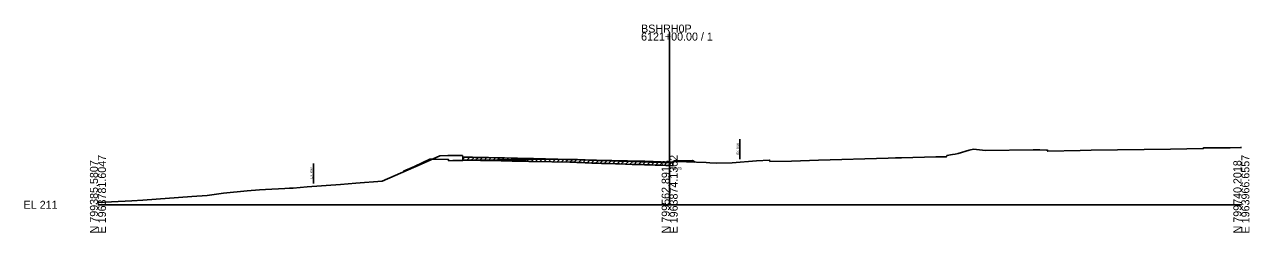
# Model space of a CAD drawing. Extents: x -26 to 1986619, y -10 to 827846.
# Drawn here: x -25.7 to 402.8, y 990.3 to 1063.1 of the extents above; entities that cross this region are included whole.
import ezdxf

# ---------------------------------------------------------------- set-up
doc = ezdxf.new("R2010")
doc.units = 0
for name, color, linetype in [('Default', 7, 'Continuous'), ('RD_EX_Road', 7, 'Continuous'), ('RD_PD_ALT5_LnLine', 7, 'Continuous'), ('RD_PD_ALT5_TrvlWay', 7, 'Continuous'), ('RD_PD_PaveDit', 7, 'Continuous'), ('RD_Sketch2', 7, 'Continuous'), ('RD_XS_ExRW', 7, 'Continuous')]:
    doc.layers.add(name, color=color, linetype=linetype)

msp = doc.modelspace()

# ---------------------------------------------------------------- linework, layer by layer
at = {"layer": 'RD_EX_Road'}
for p, q in [((200, 1000), (200, 1060.29)), ((0, 1000), (200, 1000)), ((200, 1000), (400, 1000))]:
    msp.add_line(p, q, dxfattribs=at)
at = {"layer": 'RD_PD_ALT5_LnLine'}
msp.add_lwpolyline([(0, 1000.83), (11.87, 1001.44), (15.66, 1001.6), (32.89, 1002.89), (38.19, 1003.26), (43.94, 1004.12), (52.18, 1004.88), (56.54, 1005.27), (58.65, 1005.33), (65.43, 1005.72), (66.98, 1005.8), (68.31, 1005.84), (73.24, 1006.29), (84.81, 1007.16), (90.27, 1007.58), (99.48, 1008.24), (113.12, 1014.24), (119.61, 1017.13), (122.4, 1017.3), (127.49, 1017.21), (127.59, 1016.75), (127.71, 1016.68), (128.51, 1016.69), (128.81, 1016.69), (129.12, 1016.68), (131.04, 1016.64), (132, 1016.61), (133.88, 1016.57), (136.64, 1016.53), (139.49, 1016.48), (140.33, 1016.47), (141.1, 1016.44), (142.25, 1016.41), (144.64, 1016.35), (145.06, 1016.34), (146.78, 1016.29), (147.92, 1016.27), (150.02, 1016.23), (150.74, 1016.21), (151.76, 1016.2), (152.38, 1016.21), (165.08, 1015.92), (166.86, 1015.88), (167.48, 1015.85), (167.8, 1015.83), (169.28, 1015.76), (170.48, 1015.7), (171.69, 1015.66), (172.75, 1015.62), (173.32, 1015.6), (175.07, 1015.54), (176.13, 1015.5), (177.53, 1015.47), (178.32, 1015.46), (178.95, 1015.45), (181, 1015.37), (181.77, 1015.35), (182.48, 1015.32), (184.58, 1015.24), (186.91, 1015.16), (187.84, 1015.13), (190.2, 1015.07), (191.25, 1015.04), (193.24, 1014.97), (194.95, 1014.92), (195.83, 1014.89), (196.81, 1014.86), (198.67, 1014.79), (200.24, 1014.75), (200.98, 1014.66), (201.06, 1014.75), (201.16, 1015.21), (202.12, 1015.19), (205.93, 1015.1), (212.76, 1014.8), (214.02, 1014.67), (216.39, 1014.64), (221.89, 1014.72), (230.43, 1015.41), (234.98, 1015.65), (235.08, 1015.2), (242.66, 1015.26), (252.01, 1015.61), (276.47, 1016.34), (279.02, 1016.46), (281.08, 1016.47), (293.09, 1016.76), (296.88, 1016.81), (296.98, 1017.26), (298.94, 1017.56), (299.9, 1017.74), (300.94, 1017.96), (304.8, 1019.16), (306.26, 1019.45), (310.5, 1019.01), (327.16, 1019.22), (329.09, 1019.25), (329.54, 1019.24), (331.8, 1019.19), (332.17, 1019.19), (332.27, 1018.74), (343.65, 1019.05), (347.49, 1019.09), (375.21, 1019.53), (386.67, 1019.69), (386.72, 1019.91), (396.1, 1019.99), (399.66, 1020.09), (400, 1020.1)], dxfattribs=at)
at = {"layer": 'RD_PD_PaveDit'}
for p, q in [((127.59, 1015.97), (127.59, 1016.97)), ((127.59, 1015.97), (128.32, 1016.69)), ((127.59, 1015.97), (127.71, 1015.68)), ((127.71, 1015.68), (128.51, 1015.69)), ((128.51, 1015.69), (128.81, 1015.69)), ((128.81, 1015.69), (129.12, 1015.68)), ((129.09, 1015.68), (130.07, 1016.66)), ((129.12, 1015.68), (131.04, 1015.64)), ((130.59, 1015.65), (131.57, 1016.62)), ((131.04, 1015.64), (132, 1015.61)), ((132.09, 1015.61), (133.07, 1016.59)), ((133.59, 1015.58), (134.58, 1016.56)), ((135.09, 1015.55), (136.08, 1016.54)), ((136.59, 1015.53), (137.58, 1016.51)), ((138.09, 1015.51), (139.08, 1016.49)), ((139.59, 1015.48), (140.57, 1016.46)), ((141.09, 1015.44), (142.07, 1016.41)), ((142.59, 1015.4), (143.57, 1016.37)), ((144.09, 1015.36), (145.07, 1016.34)), ((145.59, 1015.32), (146.57, 1016.29)), ((147.09, 1015.28), (148.08, 1016.26)), ((148.59, 1015.25), (149.58, 1016.24)), ((150.09, 1015.23), (151.08, 1016.21)), ((151.59, 1015.21), (152.6, 1016.21)), ((153.09, 1015.2), (154.07, 1016.18)), ((154.59, 1015.16), (155.57, 1016.14)), ((156.09, 1015.13), (157.07, 1016.11)), ((157.59, 1015.09), (158.57, 1016.07)), ((159.09, 1015.06), (160.07, 1016.04)), ((160.59, 1015.03), (161.57, 1016)), ((162.09, 1014.99), (163.07, 1015.97)), ((163.59, 1014.96), (164.57, 1015.93)), ((165.09, 1014.92), (166.07, 1015.9)), ((166.59, 1014.89), (167.55, 1015.84)), ((168.09, 1014.81), (169.05, 1015.77)), ((169.59, 1014.74), (170.55, 1015.7)), ((171.09, 1014.68), (172.06, 1015.64)), ((132, 1015.61), (133.88, 1015.57)), ((133.88, 1015.57), (136.64, 1015.53)), ((136.64, 1015.53), (139.49, 1015.48)), ((139.49, 1015.48), (140.33, 1015.47)), ((140.33, 1015.47), (141.1, 1015.44)), ((141.1, 1015.44), (142.25, 1015.41)), ((142.25, 1015.41), (144.64, 1015.35)), ((144.64, 1015.35), (145.06, 1015.34)), ((145.06, 1015.34), (146.78, 1015.29)), ((146.78, 1015.29), (147.92, 1015.27)), ((147.92, 1015.27), (150.02, 1015.23)), ((150.02, 1015.23), (150.74, 1015.21)), ((150.74, 1015.21), (151.76, 1015.2)), ((151.76, 1015.2), (152.38, 1015.21)), ((152.38, 1015.21), (165.08, 1014.92)), ((165.08, 1014.92), (166.86, 1014.88)), ((166.86, 1014.88), (167.48, 1014.85)), ((167.48, 1014.85), (167.8, 1014.83)), ((167.8, 1014.83), (169.28, 1014.76)), ((169.28, 1014.76), (170.48, 1014.7)), ((170.48, 1014.7), (171.69, 1014.66)), ((171.69, 1014.66), (172.75, 1014.62)), ((172.59, 1014.62), (173.56, 1015.59)), ((172.75, 1014.62), (173.32, 1014.6)), ((173.32, 1014.6), (175.07, 1014.54)), ((174.09, 1014.57), (175.06, 1015.54)), ((175.07, 1014.54), (176.13, 1014.5)), ((175.59, 1014.52), (176.57, 1015.49)), ((176.13, 1014.5), (177.53, 1014.47)), ((177.09, 1014.48), (178.08, 1015.47)), ((177.53, 1014.47), (178.32, 1014.46)), ((178.32, 1014.46), (178.95, 1014.45)), ((178.59, 1014.46), (179.56, 1015.43)), ((178.95, 1014.45), (181, 1014.37)), ((180.09, 1014.41), (181.06, 1015.37)), ((181, 1014.37), (181.77, 1014.35)), ((181.59, 1014.35), (182.56, 1015.32)), ((181.77, 1014.35), (182.48, 1014.32)), ((182.48, 1014.32), (184.58, 1014.24)), ((183.09, 1014.3), (184.06, 1015.26)), ((184.58, 1014.24), (186.91, 1014.16)), ((184.59, 1014.24), (185.56, 1015.21)), ((186.09, 1014.19), (187.06, 1015.16)), ((186.91, 1014.16), (187.84, 1014.13)), ((187.59, 1014.14), (188.57, 1015.11)), ((187.84, 1014.13), (190.2, 1014.07)), ((189.09, 1014.1), (190.07, 1015.07)), ((190.2, 1014.07), (191.25, 1014.04)), ((190.59, 1014.06), (191.57, 1015.03)), ((191.25, 1014.04), (193.24, 1013.97)), ((192.09, 1014.01), (193.06, 1014.98)), ((193.24, 1013.97), (194.95, 1013.92)), ((193.59, 1013.96), (194.56, 1014.93)), ((194.95, 1013.92), (195.83, 1013.89)), ((195.09, 1013.91), (196.06, 1014.88)), ((195.83, 1013.89), (196.81, 1013.86)), ((196.59, 1013.86), (197.56, 1014.83)), ((196.81, 1013.86), (198.67, 1013.79)), ((198.09, 1013.81), (199.06, 1014.78)), ((198.67, 1013.79), (200.24, 1013.75)), ((199.59, 1013.76), (200.54, 1014.71)), ((200.24, 1013.75), (200.98, 1013.66)), ((200.98, 1013.66), (201.06, 1013.89)), ((201.06, 1014.89), (201.06, 1013.89))]:
    msp.add_line(p, q, dxfattribs=at)
at = {"layer": 'RD_Sketch2'}
msp.add_lwpolyline([(106.89, 1011.8), (110.77, 1013.38), (116.12, 1016.01), (117.12, 1015.98), (117.86, 1015.96), (122.17, 1015.86), (122.67, 1015.86), (122.75, 1015.36), (124.18, 1015.46), (124.8, 1015.47), (127.69, 1015.53), (130.97, 1015.58), (159.18, 1016.02), (159.58, 1016.01), (163.47, 1015.92), (190.69, 1015.26), (191.36, 1015.24), (200, 1014.99), (200, 1014.99), (200, 1014.99), (201.41, 1014.88), (201.5, 1015.38), (201.99, 1015.38), (202.62, 1015.39), (206.98, 1015.45), (207.97, 1015.47), (208.94, 1014.98)], dxfattribs=at)
at = {"layer": 'RD_XS_ExRW'}
for p, q in [((224.49, 1015.93), (224.49, 1022.93)), ((75.4, 1007.46), (75.4, 1014.46))]:
    msp.add_line(p, q, dxfattribs=at)

# ---------------------------------------------------------------- texts
at = {"layer": 'Default'}
msp.add_text('-', height=0.0001, dxfattribs=at).set_placement((0, 1000))
at = {"layer": 'RD_EX_Road'}
for s, p in [('BSHRH0P', (190, 1060.29)), ('6121+00.00 / 1', (190, 1057.49)), ('EL 211', (-26, 998.6))]:
    msp.add_text(s, height=2.8, dxfattribs=at).set_placement(p)
for s, p in [('E 1963781.6047', (2.8, 990)), ('E 1963874.1302', (202.8, 990)), ('E 1963966.6557', (402.8, 990)), ('N 799385.5807', (0, 990)), ('N 799562.8913', (200, 990)), ('N 799740.2018', (400, 990))]:
    msp.add_text(s, height=2.8, rotation=90, dxfattribs=at).set_placement(p)
at = {"layer": 'RD_PD_ALT5_TrvlWay'}
msp.add_text('225.75', height=1, dxfattribs=at).set_placement((200, 1012.25))
at = {"layer": 'RD_XS_ExRW'}
for p in [(224.24, 1017.6), (75.02, 1009.13)]:
    msp.add_text('EX. R/W ', height=0.75, rotation=90, dxfattribs=at).set_placement(p)

doc.saveas('drawing.dxf')
